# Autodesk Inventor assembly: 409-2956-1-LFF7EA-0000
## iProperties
Created: 2010-09
Part Number: 409-2956-1-LFF7EA-0000
Document SubType Name: Assembly
Designer: S. Boerckel
Mass: 3.23126e+06 g
Surface Area: 838750 cm^2
Volume: 427218 cm^3
Density: 7.56349 g/cm^3
Description: CONTROLS & ELECTRICAL
Material: ASSEMBLY
SMR: =<MATERIAL>
Author: S. Boerckel
Revision Number: 0
